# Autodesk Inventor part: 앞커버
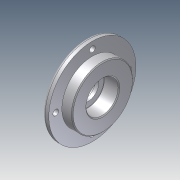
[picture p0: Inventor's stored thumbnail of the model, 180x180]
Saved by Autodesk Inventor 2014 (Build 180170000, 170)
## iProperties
Company: 한국ATC센터
Created: 2014-01
Part Number: 앞커버
Document SubType Name: Modeling
Designer: KYOUNG IL JANG
Density: 7.86 g/cm^3
Material: 강철, 연강
Mass: 698.73 g
Surface Area: 235.103 cm^2
Volume: 88.8969 cm^3
Vendor: CBT Solutions
Appearance: 강철
Author: KYOUNG IL JANG
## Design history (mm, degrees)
sketch "스케치1"
  geometry: L1 (-15, -35)-(-15, 35) reference; L2 (-15, 35)-(67, 35) reference; L3 (-3, 25)-(-3, -10.613) reference; L4 (0, 0)-(-32, 0); L5 (-3, 0)-(-3, 35); L6 (-3, 35)-(-15, 35); L7 (-15, 35)-(-15, 50); L8 (-15, 50)-(-22, 50); L9 (-22, 50)-(-22, 22.5); L10 (-22, 22.5)-(-32, 22.5); L11 (-32, 22.5)-(-32, 0); L12 (-3, 18.5)-(-20, 18.5); L13 (-20, 18.5)-(-20, 12.5); L14 (-20, 12.5)-(-24, 12.5); L15 (-24, 12.5)-(-24, 16); L16 (-24, 16)-(-32, 16)
  constraints: 28 end point, 7 perpendicular, 6 parallel, 5 point on line, 1 horizontal, 1 other
  dimensions: "d0" = 7 distance of L7.end L8.end; "d1" = 45 diameter of L10 L4; "d2" = 10 distance of L9.end L10.end; "d3" = 37 diameter of L12 L4; "d4" = 17 distance of L12.start L12.end; "d5" = 32 diameter of L16 L4; "d6" = 8 distance of L15.end L16.end; "d7" = 25 diameter of L14 L4; "d8" = 100 diameter of L8 L4
revolve "회전1" sketch "스케치1" stored, may be unused: angle "d9" = 90 deg
fillet "모깎기1" dims "d10" = 3, "d11" = 0.3
chamfer "모따기1" distance "d12" = 1; stored, may be unused: second distance "d13" = 2, angle "d14" = 45 deg
sketch "스케치2"
  geometry: 2 further points
  constraints: 1 vertical alignment
  dimensions: "d15" = 42 distance of point (0, 0) point (0, 42)
hole "구멍1" sketch "스케치2" at (0, 42) diameter "d16" = 6.6; stored, may be unused: countersink angle "d20" = 90 deg, drill point angle "d22" = 118 deg; dims "d17" = 6, "d18" = 4, "d19" = 2, "d21" = 8
node "솔리드1"
pattern_circular "원형 패턴1" dims angle "d24" = 360 deg
node "참조1"
node "참조2"
